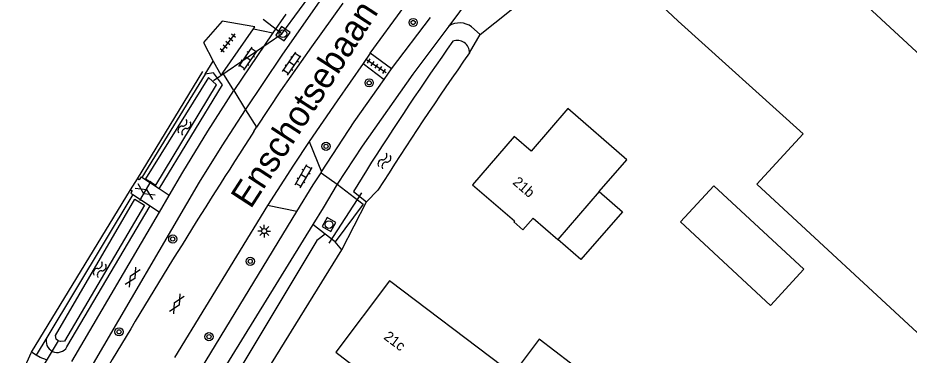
# Model space of a CAD drawing. Extents: x 136000 to 138005, y 398500 to 400500.
# Drawn here: x 137178.2 to 137265.3, y 398623.5 to 398656.4 of the extents above; entities that cross this region are included whole.
import ezdxf

# ---------------------------------------------------------------- set-up
doc = ezdxf.new("R2010")
doc.units = 0
for name, color, linetype in [('gg-afsc-erfafscheiding', 7, 'Continuous'), ('gg-anno-huisnummerreeks BGT', 7, 'Continuous'), ('gg-anno-openbare ruimte label', 7, 'Continuous'), ('gg-bbg-bijgebouw', 7, 'Continuous'), ('gg-bbg-hoofdgebouw', 7, 'Continuous'), ('gg-bbg-onder overbouw', 7, 'Continuous'), ('gg-bbg-pand overbouw', 7, 'Continuous'), ('gg-knt-verharding', 7, 'Continuous'), ('gg-kntw-bovenkant insteek waterloop', 7, 'Continuous'), ('gg-kntw-greppel-droge sloot', 7, 'Continuous'), ('gg-kntw-waterlijn', 7, 'Continuous'), ('gg-kwrk-duiker nz buis', 7, 'Continuous'), ('gt-grn-vlakafsluiter', 7, 'Continuous'), ('gt-grn-weggrens', 7, 'Continuous'), ('gt-symb-boom', 7, 'Continuous'), ('gt-symb-gesloten verharding', 7, 'Continuous'), ('gt-symb-klinker verharding', 7, 'Continuous'), ('gt-symb-lichtmast', 7, 'Continuous'), ('gt-symb-rioolschacht', 7, 'Continuous'), ('gt-symb-tegel verharding', 7, 'Continuous'), ('gt-symb-watersymbool', 7, 'Continuous')]:
    doc.layers.add(name, color=color, linetype=linetype)

# ---------------------------------------------------------------- blocks, each defined once
blk = doc.blocks.new('gt0-BOOM')
at = {"layer": 'gt-symb-boom'}
for radius in [0.4, 0.2]:
    blk.add_circle((0, 0), radius, dxfattribs=at)
blk = doc.blocks.new('gt0-TEG1')
at = {"layer": 'gt-symb-tegel verharding'}
for p, q in [((-1.125, 0), (1.125, 0)), ((-0.9, -0.25), (-0.9, 0.25)), ((-0.45, -0.25), (-0.45, 0.25)), ((0, -0.25), (0, 0.25)), ((0.45, -0.25), (0.45, 0.25)), ((0.9, -0.25), (0.9, 0.25))]:
    blk.add_line(p, q, dxfattribs=at)
blk = doc.blocks.new('gt0-RS')
at = {"layer": 'gt-symb-rioolschacht'}
blk.add_lwpolyline([(-0.5, -0.5), (0.5, -0.5), (0.5, 0.5), (-0.5, 0.5)], close=True, dxfattribs=at)
blk.add_circle((0, 0), 0.375, dxfattribs=at)
blk = doc.blocks.new('gt0-KL1')
at = {"layer": 'gt-symb-klinker verharding'}
for p, q in [((-1.15, 0.3), (1.15, 0.3)), ((-1, -0.3), (-1, 0.3)), ((-0.5, 0.3), (-0.5, 0.45)), ((0, -0.3), (0, 0.3)), ((0.5, 0.3), (0.5, 0.45)), ((1, -0.3), (1, 0.3)), ((-1.15, -0.3), (1.15, -0.3)), ((-0.5, -0.45), (-0.5, -0.3)), ((0.5, -0.45), (0.5, -0.3))]:
    blk.add_line(p, q, dxfattribs=at)
blk = doc.blocks.new('gt0-WA')
at = {"layer": 'gt-symb-watersymbool'}
for centre, start, end in [((-0.323, 0.022), 28.07249, 151.92751), ((0.427, 0.422), 208.07248, 331.92751), ((-0.323, -0.428), 28.07249, 151.92751), ((0.427, -0.028), 208.07248, 331.92751)]:
    blk.add_arc(centre, 0.425, start, end, dxfattribs=at)
blk = doc.blocks.new('gt0-GESVH1')
at = {"layer": 'gt-symb-gesloten verharding'}
for p, q in [((-0.992, -0.261), (0.008, 0.239)), ((0.008, -0.261), (-0.992, 0.239)), ((0.008, 0.239), (1.008, -0.261)), ((1.008, 0.239), (0.008, -0.261))]:
    blk.add_line(p, q, dxfattribs=at)
blk = doc.blocks.new('gt0-LMAST')
at = {"layer": 'gt-symb-lichtmast'}
for p, q in [((-0.182, 0.173), (-0.447, 0.438)), ((-0.005, 0.246), (-0.005, 0.621)), ((0.172, 0.173), (0.437, 0.438)), ((-0.255, -0.004), (-0.63, -0.004)), ((-0.182, -0.181), (-0.447, -0.446)), ((-0.005, -0.254), (-0.005, -0.629)), ((0.437, -0.446), (0.172, -0.181)), ((0.245, -0.004), (0.62, -0.004))]:
    blk.add_line(p, q, dxfattribs=at)
blk.add_circle((-0.005, -0.004), 0.25, dxfattribs=at)

msp = doc.modelspace()

# ---------------------------------------------------------------- linework, layer by layer
at = {"layer": 'gg-afsc-erfafscheiding'}
for p, q in [((137189.849, 398640.686), (137196.263, 398651.16)), ((137189.189, 398639.607), (137189.849, 398640.686)), ((137179.483, 398623.758), (137189.189, 398639.607)), ((137178.262, 398620.988), (137179.483, 398623.758))]:
    msp.add_line(p, q, dxfattribs=at)
at = {"layer": 'gg-bbg-bijgebouw'}
msp.add_lwpolyline([(137242.938, 398636.457), (137246.198, 398639.992), (137255.007, 398631.851), (137251.746, 398628.316), (137242.938, 398636.457)], dxfattribs=at)
at = {"layer": 'gg-bbg-hoofdgebouw'}
for points in [[(137242.72, 398656.06), (137254.952, 398645.064), (137250.418, 398640.159), (137267.39, 398624.464), (137281.032, 398639.25), (137251.855, 398666.177), (137257.987, 398672.821), (137250.63, 398679.61)], [(137240.611, 398676.323), (137240.58, 398676.29), (137248.17, 398669.07), (137239.09, 398659.51), (137242.72, 398656.06)], [(137235.011, 398639.42), (137237.704, 398642.532), (137231.931, 398647.524), (137228.337, 398643.354), (137226.68, 398644.805), (137222.625, 398640.097), (137226.712, 398636.561), (137226.647, 398636.485), (137227.553, 398635.701), (137228.534, 398636.834), (137230.958, 398634.737)], [(137216.21, 398618.417), (137214.789, 398616.533), (137218.406, 398613.805), (137219.841, 398615.688), (137220.345, 398615.31), (137224.164, 398620.394), (137225.131, 398619.667), (137224.71, 398619.107), (137233.947, 398612.16), (137238.334, 398618.004), (137229.132, 398625.018), (137226.289, 398621.247), (137225.334, 398621.965), (137225.61, 398622.332), (137214.484, 398630.699), (137209.241, 398623.761), (137216.21, 398618.417)]]:
    msp.add_lwpolyline(points, dxfattribs=at)
at = {"layer": 'gg-bbg-onder overbouw'}
msp.add_line((137235.011, 398639.42), (137230.958, 398634.737), dxfattribs=at)
at = {"layer": 'gg-bbg-pand overbouw'}
msp.add_lwpolyline([(137235.011, 398639.42), (137237.27, 398637.465), (137233.217, 398632.782), (137230.958, 398634.737)], dxfattribs=at)
at = {"layer": 'gg-knt-verharding'}
for p, q in [((137224.612, 398661.328), (137220.299, 398655.582)), ((137204.369, 398656.731), (137203.085, 398654.933)), ((137212.613, 398652.921), (137215.889, 398657.423)), ((137214.704, 398651.416), (137218.494, 398656.431)), ((137198.217, 398651.007), (137201.196, 398655.301)), ((137203.085, 398654.933), (137199.275, 398649.276)), ((137201.196, 398655.301), (137203.085, 398654.933)), ((137223.354, 398654.751), (137222.53, 398655.492)), ((137212.613, 398652.921), (137211.91, 398651.932)), ((137214.704, 398651.416), (137212.613, 398652.921)), ((137211.91, 398651.932), (137213.974, 398650.379)), ((137199.275, 398649.276), (137198.217, 398651.007)), ((137213.974, 398650.379), (137214.704, 398651.416)), ((137200.406, 398647.389), (137201.511, 398645.697)), ((137201.248, 398645.297), (137201.511, 398645.697)), ((137206.657, 398644.307), (137207.866, 398641.358)), ((137207.807, 398641.268), (137207.866, 398641.358)), ((137191.972, 398639.71), (137190.289, 398640.814)), ((137192.969, 398639.057), (137191.972, 398639.71)), ((137189.391, 398639.155), (137191.097, 398638.03)), ((137192.012, 398637.427), (137192.969, 398639.057)), ((137191.097, 398638.03), (137192.012, 398637.427)), ((137202.585, 398638.053), (137193.48, 398623.231)), ((137205.428, 398637.468), (137202.585, 398638.053)), ((137183.455, 398622.838), (137192.012, 398637.427)), ((137194.435, 398619.441), (137205.428, 398637.468)), ((137207.016, 398636.202), (137196.029, 398618.455)), ((137208.216, 398635.277), (137207.016, 398636.202)), ((137209.188, 398634.527), (137208.216, 398635.277)), ((137179.96, 398623.47), (137179.483, 398623.758))]:
    msp.add_line(p, q, dxfattribs=at)
for points in [[(137200.406, 398647.389), (137204.014, 398652.756), (137207.737, 398658.045)], [(137209.944, 398657.827), (137206.875, 398653.554), (137203.85, 398649.25), (137201.511, 398645.697)], [(137201.196, 398655.301), (137201.347, 398655.519), (137198.146, 398656.044), (137196.316, 398653.961), (137197.274, 398652.17)], [(137220.299, 398655.582), (137216.77, 398650.88), (137211.83, 398643.86), (137209.377, 398640.146)], [(137197.274, 398652.17), (137198.035, 398650.745), (137198.217, 398651.007)], [(137211.91, 398651.932), (137209.367, 398648.291), (137206.657, 398644.307)], [(137207.866, 398641.358), (137211.05, 398646.23), (137213.974, 398650.379)], [(137192.969, 398639.057), (137194.29, 398641.31), (137196.744, 398645.317), (137199.275, 398649.276)], [(137185.336, 398622.264), (137195.923, 398640.354), (137198.14, 398643.887), (137200.406, 398647.389)], [(137206.657, 398644.307), (137205.112, 398641.99), (137202.585, 398638.053)], [(137205.428, 398637.468), (137207.03, 398640.08), (137207.807, 398641.268)], [(137190.289, 398640.814), (137190.229, 398640.853), (137190.017, 398640.574), (137189.849, 398640.686)], [(137209.377, 398640.146), (137208.03, 398637.84), (137207.016, 398636.202)], [(137209.377, 398640.146), (137211.923, 398638.203), (137209.188, 398634.527)], [(137189.189, 398639.607), (137189.344, 398639.501), (137189.193, 398639.285), (137189.391, 398639.155)], [(137180.951, 398622.99), (137180.353, 398623.233), (137179.96, 398623.47)]]:
    msp.add_lwpolyline(points, dxfattribs=at)
for centre, radius, start, end in [((137221.35, 398653.94), 1.95, 52.75551, 122.62429), ((137768.741, 398276.623), 676.734, 146.990074, 149.357554)]:
    msp.add_arc(centre, radius, start, end, dxfattribs=at)
at = {"layer": 'gg-kntw-bovenkant insteek waterloop'}
for p, q in [((137196.484, 398650.886), (137190.289, 398640.814)), ((137189.391, 398639.155), (137180.995, 398625.191)), ((137182.961, 398624.26), (137191.097, 398638.03))]:
    msp.add_line(p, q, dxfattribs=at)
msp.add_lwpolyline([(137191.972, 398639.71), (137198.182, 398649.832), (137197.295, 398651), (137196.484, 398650.886)], dxfattribs=at)
msp.add_arc((137182.02, 398624.815), 1.092, 159.86688, 329.4533, dxfattribs=at)
at = {"layer": 'gg-kntw-greppel-droge sloot'}
for p, q in [((137212.257, 398638.416), (137213.37, 398639.549)), ((137209.846, 398633.735), (137209.188, 398634.527))]:
    msp.add_line(p, q, dxfattribs=at)
for points in [[(137212.238, 398641.497), (137210.981, 398639.44), (137212.257, 398638.416)], [(137208.216, 398635.277), (137207.39, 398634.644), (137197.818, 398618.694), (137197.701, 398617.459)], [(137198.74, 398616.84), (137199.72, 398617.445), (137209.846, 398633.735)]]:
    msp.add_lwpolyline(points, dxfattribs=at)
for centre, radius, start, end in [((137487.899, 398465.729), 326.93, 144.8178, 147.47742), ((137221.119, 398652.966), 1.211, 359.97163, 110.67079), ((137469.866, 398477.946), 303.159, 144.73795, 147.78736)]:
    msp.add_arc(centre, radius, start, end, dxfattribs=at)
at = {"layer": 'gg-kntw-waterlijn'}
for points in [[(137196.789, 398650.545), (137190.639, 398640.665), (137191.639, 398640.043), (137197.581, 398649.845), (137196.789, 398650.545)], [(137189.596, 398638.698), (137190.535, 398638.103), (137182.726, 398624.834), (137182.34, 398624.789), (137182.091, 398624.85), (137181.903, 398625.025), (137181.856, 398625.365), (137189.596, 398638.698)]]:
    msp.add_lwpolyline(points, dxfattribs=at)
at = {"layer": 'gg-kwrk-duiker nz buis'}
for p, q in [((137203.988, 398654.825), (137202.154, 398656.236)), ((137197.303, 398650.284), (137203.988, 398654.825)), ((137190.092, 398638.554), (137191.196, 398640.434)), ((137211.774, 398639.298), (137208.56, 398634.404)), ((137182.091, 398624.85), (137177.968, 398618.036))]:
    msp.add_line(p, q, dxfattribs=at)
msp.add_lwpolyline([(137203.988, 398654.825), (137216.066, 398671.239), (137215.247, 398675.418)], dxfattribs=at)
at = {"layer": 'gt-grn-vlakafsluiter'}
for p, q in [((137223.354, 398654.751), (137227.821, 398658.325)), ((137222.33, 398652.965), (137223.354, 398654.751)), ((137196.484, 398650.886), (137197.274, 398652.17)), ((137209.846, 398633.735), (137212.257, 398638.416)), ((137180.995, 398625.191), (137179.96, 398623.47))]:
    msp.add_line(p, q, dxfattribs=at)
at = {"layer": 'gt-grn-weggrens'}
for p, q in [((137199.275, 398649.276), (137200.406, 398647.389)), ((137207.807, 398641.268), (137209.377, 398640.146))]:
    msp.add_line(p, q, dxfattribs=at)

# ---------------------------------------------------------------- block references
at = {"layer": 'gt-symb-boom'}
for p in [(137216.815, 398655.933), (137212.513, 398650.035), (137208.298, 398643.841), (137193.308, 398634.794), (137200.885, 398632.619), (137188.06, 398625.732), (137196.849, 398625.264)]:
    msp.add_blockref('gt0-BOOM', p, dxfattribs=at)
at = {"layer": 'gt-symb-gesloten verharding'}
for p, rotation in [((137190.614, 398639.426), -33.45160145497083), ((137189.374, 398631.074), 59.40956459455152), ((137193.692, 398628.469), 59.40956459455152)]:
    msp.add_blockref('gt0-GESVH1', p, dxfattribs=dict(at, rotation=rotation))
at = {"layer": 'gt-symb-klinker verharding'}
for p, rotation in [((137200.66, 398652.404), 55.26137471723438), ((137204.947, 398651.914), 55.46787543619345), ((137206.102, 398640.93), 59.66519417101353)]:
    msp.add_blockref('gt0-KL1', p, dxfattribs=dict(at, rotation=rotation))
at = {"layer": 'gt-symb-lichtmast'}
msp.add_blockref('gt0-LMAST', (137202.253, 398635.574), dxfattribs=at)
at = {"layer": 'gt-symb-rioolschacht'}
for p, rotation in [((137204.082, 398654.829), 55.59476571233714), ((137208.584, 398636.207), 150.9007199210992)]:
    msp.add_blockref('gt0-RS', p, dxfattribs=dict(at, rotation=rotation))
at = {"layer": 'gt-symb-tegel verharding'}
for p, rotation in [((137198.7, 398653.945), -127.56859202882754), ((137213.224, 398651.667), -33.42003119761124)]:
    msp.add_blockref('gt0-TEG1', p, dxfattribs=dict(at, rotation=rotation))
at = {"layer": 'gt-symb-watersymbool'}
for p, rotation in [((137194.416, 398645.652), 59.40956459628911), ((137213.975, 398642.371), 59.40956459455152), ((137186.141, 398631.765), 59.40956459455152)]:
    msp.add_blockref('gt0-WA', p, dxfattribs=dict(at, rotation=rotation))

# ---------------------------------------------------------------- texts
at = {"layer": 'gg-anno-huisnummerreeks BGT'}
for s, rotation, p in [('21b', 319.3, (137226.473, 398640.222)), ('21c', 322.9, (137213.855, 398625.099))]:
    msp.add_text(s, height=1, rotation=rotation, dxfattribs=at).set_placement(p)
at = {"layer": 'gg-anno-openbare ruimte label'}
msp.add_text('Enschotsebaan', height=2.5, rotation=57, dxfattribs=at).set_placement((137200.932, 398637.656))

doc.saveas('drawing.dxf')
